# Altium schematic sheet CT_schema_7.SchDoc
size 287 x 160 mm
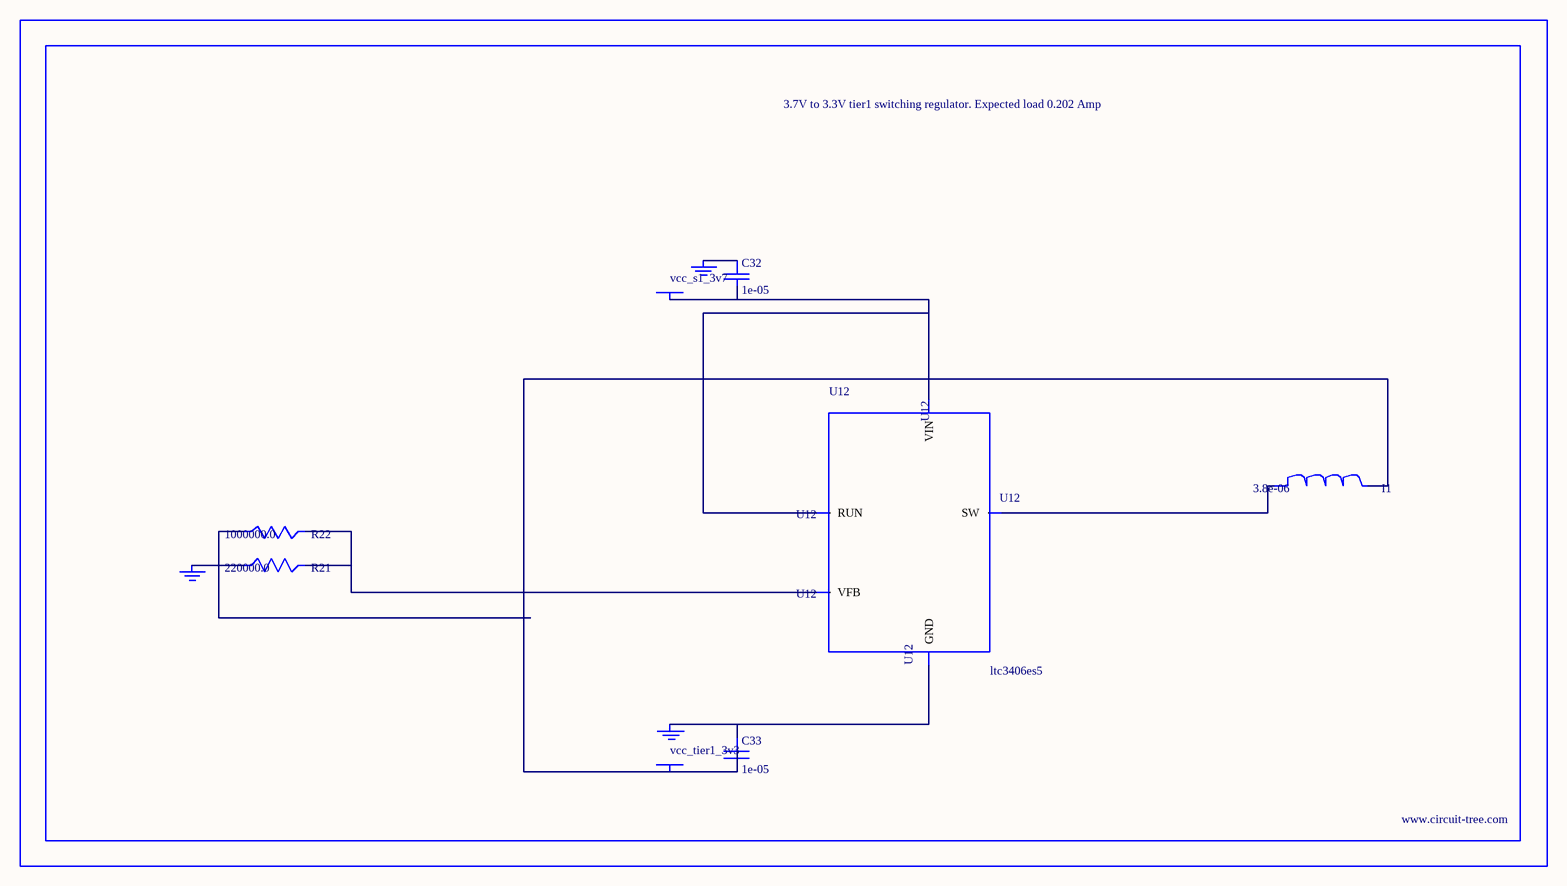
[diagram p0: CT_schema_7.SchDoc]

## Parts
BORDER6  (no value)
C32  1e-05  [C0805]
C33  1e-05  [C0805]
GND_INSTANCE_6_0  (no value)
GND_INSTANCE_6_1  (no value)
GND_INSTANCE_6_2  (no value)
I1  3.8e-06  [DR1040]
POWER_INSTANCE_6_0  vcc_tier1_3v3
POWER_INSTANCE_6_1  vcc_s1_3v7
R21  220000.0  [R0603]
R22  1000000.0  [R0603]
U12  ltc3406es5  [TSOT-23-5]

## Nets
NetC32_1: C32.1 GND_INSTANCE_6_1.0(GND)
NetC32_2: C32.2 POWER_INSTANCE_6_1.0(PWR) U12.1(RUN) U12.4(VIN)
NetC33_1: C33.1 GND_INSTANCE_6_0.0(GND) U12.2(GND)
NetC33_2: C33.2 I1.2 POWER_INSTANCE_6_0.0(PWR) R22.1
NetGND_INSTANCE_6_2_0: GND_INSTANCE_6_2.0(GND) R21.1
NetI1_1: I1.1 U12.3(SW)
NetR21_2: R21.2 R22.2 U12.5(VFB)

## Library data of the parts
BORDER6 = BORDER_PAGE6
C32 C33 = C0805C106K8RACTU
GND_INSTANCE_6_0-GND_INSTANCE_6_2 = GND
I1 = DR1040-3R8-R
POWER_INSTANCE_6_0 POWER_INSTANCE_6_1 = PWR
R21 = RC0603JR-07220KL
R22 = RC0603JR-071ML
